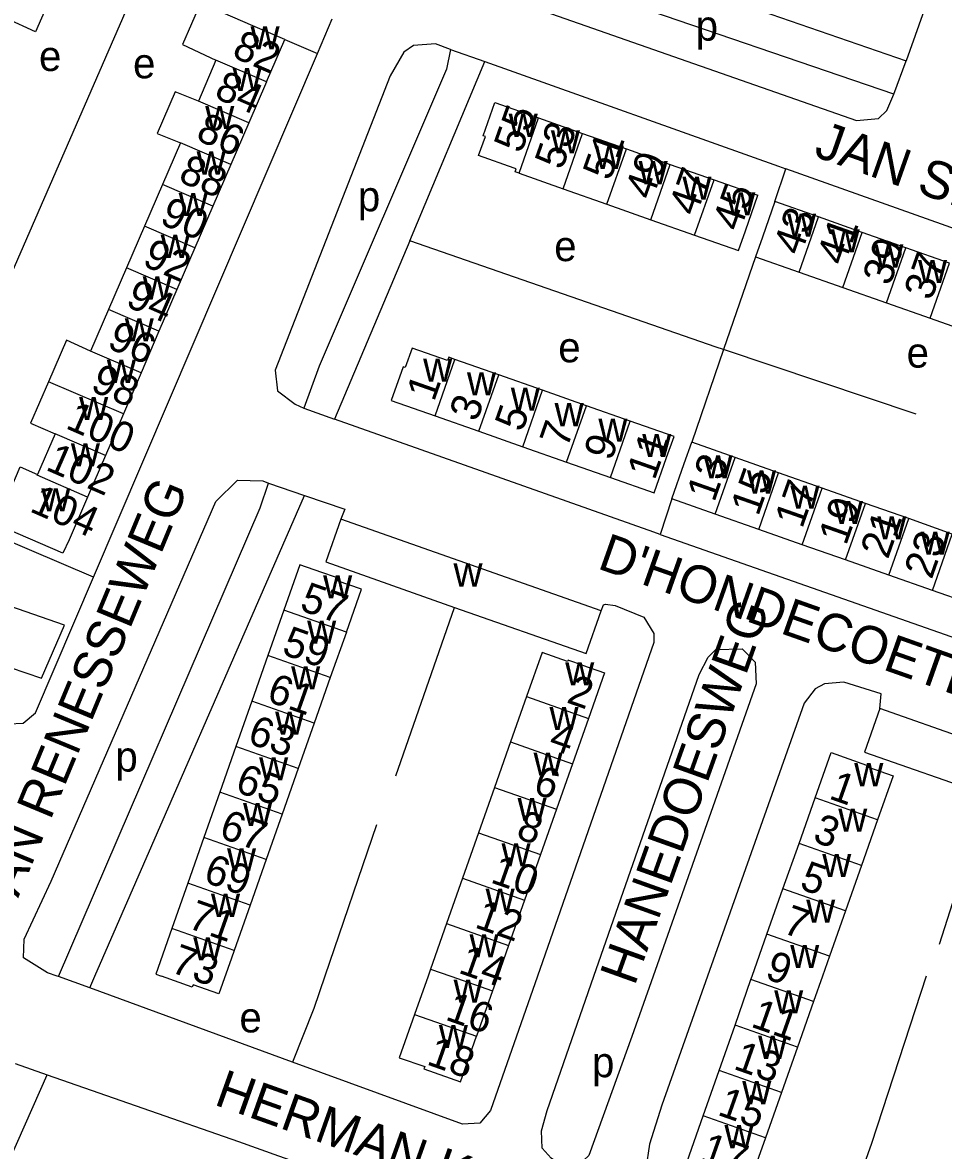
# Model space of a CAD drawing. Extents: x 162804 to 165059, y 381530 to 382901.
# Drawn here: x 163644.1 to 163766.6, y 381726.8 to 381876.8 of the extents above; entities that cross this region are included whole.
import ezdxf

# ---------------------------------------------------------------- set-up
doc = ezdxf.new("R2010")
doc.units = 0
for name, color, linetype in [('BLT_Basislijn', 7, 'Continuous'), ('BLT_Bebouwing', 7, 'Continuous'), ('BLT_Centroide', 7, 'Continuous'), ('BLT_Huisnummer', 7, 'Continuous'), ('BLT_Huisnummer_ tussenligend', 7, 'Continuous'), ('BLT_Onderverdeling_panden', 7, 'Continuous'), ('BLT_Straatnaam', 7, 'Continuous')]:
    doc.layers.add(name, color=color, linetype=linetype)

msp = doc.modelspace()

# ---------------------------------------------------------------- linework, layer by layer
at = {"layer": 'BLT_Basislijn'}
for p, q in [((163629.47, 381813.33), (163659.78, 381882.71)), ((163760.01, 381867.25), (163713.3, 381883.25)), ((163738.48, 381879.67), (163761.67, 381871.69)), ((163683.32, 381872.7), (163685.28, 381877.3)), ((163678.98, 381874.55), (163683.32, 381872.7)), ((163701.04, 381873.2), (163705.58, 381871.61)), ((163653.55, 381803.05), (163683.32, 381872.7)), ((163695.62, 381847.77), (163705.58, 381871.61)), ((163760.01, 381867.25), (163761.67, 381871.69)), ((163744.19, 381852.99), (163745.66, 381857.35)), ((163695.62, 381847.77), (163685.59, 381824.07)), ((163741.61, 381845.66), (163737.37, 381833.31)), ((163737.37, 381833.31), (163733.13, 381820.98)), ((163762.97, 381824.74), (163737.37, 381833.31)), ((163681.54, 381825.53), (163685.59, 381824.07)), ((163676.84, 381815.54), (163681.63, 381813.9)), ((163653.55, 381803.05), (163629.47, 381813.33)), ((163653.73, 381750), (163681.63, 381813.9)), ((163730.48, 381813.47), (163728.92, 381808.74)), ((163693.74, 381776.62), (163701.56, 381799.04)), ((163766.09, 381754.26), (163772.39, 381774.1)), ((163691.19, 381770.14), (163684.3, 381750)), ((163648.87, 381749.95), (163648.71, 381750)), ((163653.04, 381748.44), (163648.87, 381749.95)), ((163653.04, 381748.44), (163653.73, 381750)), ((163680.03, 381738.55), (163653.04, 381748.44)), ((163643.14, 381738.37), (163647.37, 381736.86)), ((163638.42, 381716.6), (163647.37, 381736.86))]:
    msp.add_line(p, q, dxfattribs=at)
for points in [[(163772.36, 381901.83), (163772.22, 381901.46), (163761.67, 381871.69)], [(163713.58, 381878.28), (163755.04, 381863.76), (163757.97, 381864.02), (163759.09, 381865.09), (163760.01, 381867.25)], [(163701.04, 381873.2), (163699.05, 381873.95), (163696.12, 381873.75), (163694.82, 381872.84), (163693.02, 381869.72), (163677.71, 381830.57), (163678.01, 381827.83), (163680.38, 381826.06), (163681.54, 381825.53)], [(163701.04, 381873.2), (163700.49, 381870.58), (163683.54, 381831.12), (163681.54, 381825.53)], [(163705.58, 381871.61), (163744.66, 381857.71), (163745.66, 381857.35)], [(163805.79, 381835.96), (163804.41, 381836.45), (163745.66, 381857.35)], [(163737.37, 381833.31), (163736.36, 381833.65), (163695.62, 381847.77)], [(163605.48, 381823.75), (163598.15, 381806.85), (163597.24, 381803.85), (163596.76, 381800.38), (163598.72, 381798.05), (163642.29, 381783.55), (163644.18, 381783.63), (163645.81, 381785.02), (163653.55, 381803.05)], [(163728.92, 381808.74), (163728.08, 381809.04), (163685.59, 381824.07)], [(163648.71, 381750), (163647.44, 381750.44), (163644.23, 381752.43), (163644.33, 381754.93), (163647.92, 381762.61), (163669.82, 381813.12), (163672.71, 381815.94), (163676.05, 381815.88), (163676.84, 381815.54)], [(163648.87, 381749.95), (163675.72, 381812.25), (163676.84, 381815.54)], [(163681.63, 381813.9), (163686.98, 381812.1), (163686.46, 381810.78)], [(163728.92, 381808.74), (163787.79, 381788.07), (163788.98, 381787.65)], [(163721.08, 381798.59), (163721.37, 381799.36), (163721.66, 381799.46), (163722.93, 381799.3), (163726.76, 381797.74), (163728.1, 381795.55), (163728.06, 381794.38), (163712.6, 381750)], [(163720.12, 381750), (163734.12, 381790.09), (163735.29, 381792.42), (163736.31, 381793.44), (163739.82, 381793.53), (163741.55, 381791.74), (163741.68, 381788.85), (163727.98, 381750)], [(163758.13, 381785.57), (163758.32, 381787.53), (163753.35, 381789.07), (163750.8, 381788.88), (163749.53, 381788.21), (163748.1, 381786.3), (163735.23, 381750)], [(163684.3, 381750), (163682.84, 381745.72), (163680.03, 381738.55)], [(163712.6, 381750), (163706.37, 381732.12), (163704.95, 381730.44), (163702.62, 381730.31), (163680.03, 381738.55)], [(163727.98, 381750), (163725.15, 381741.98), (163719.43, 381726.17), (163718.73, 381725.47), (163717.8, 381725.09), (163715.67, 381724.95), (163714.42, 381725.8), (163713.22, 381727.12), (163713.12, 381729.45), (163713.87, 381732.12), (163720.12, 381750)], [(163735.23, 381750), (163729.15, 381732.86), (163727.51, 381727.67), (163727.02, 381724.4), (163727.01, 381723.23), (163727.33, 381722.52), (163728.51, 381721.39), (163729.94, 381720.75), (163751.94, 381713.38)], [(163764.29, 381750), (163757.03, 381727.74), (163751.94, 381713.38)], [(163647.37, 381736.86), (163672.82, 381728.03), (163678.15, 381726.12), (163737.77, 381705.14), (163743.56, 381703.1), (163751.63, 381700.04), (163751.28, 381698.53)]]:
    msp.add_lwpolyline(points, dxfattribs=at)
at = {"layer": 'BLT_Bebouwing'}
for p, q in [((163676.54, 381868.89), (163678.98, 381874.55)), ((163669.83, 381871.79), (163667.49, 381866.36)), ((163676.54, 381868.89), (163674.2, 381863.47)), ((163712.76, 381864.11), (163718.59, 381862.05)), ((163674.2, 381863.47), (163671.81, 381857.93)), ((163718.59, 381862.05), (163724.43, 381859.99)), ((163665.1, 381860.82), (163662.71, 381855.28)), ((163724.43, 381859.99), (163730.26, 381857.94)), ((163671.81, 381857.93), (163669.42, 381852.38)), ((163710.17, 381856.75), (163716, 381854.69)), ((163730.26, 381857.94), (163736.09, 381855.88)), ((163662.71, 381855.28), (163660.32, 381849.73)), ((163736.09, 381855.88), (163741.92, 381853.83)), ((163716, 381854.69), (163721.83, 381852.64)), ((163669.42, 381852.38), (163667.03, 381846.84)), ((163721.83, 381852.64), (163727.67, 381850.58)), ((163750, 381850.95), (163744.19, 381852.99)), ((163727.67, 381850.58), (163733.5, 381848.53)), ((163755.8, 381848.9), (163750, 381850.95)), ((163660.32, 381849.73), (163657.93, 381844.18)), ((163761.61, 381846.85), (163755.8, 381848.9)), ((163667.03, 381846.84), (163664.64, 381841.29)), ((163767.41, 381844.81), (163761.61, 381846.85)), ((163741.61, 381845.66), (163747.41, 381843.61)), ((163657.93, 381844.18), (163655.54, 381838.64)), ((163747.41, 381843.61), (163753.22, 381841.57)), ((163664.64, 381841.29), (163662.25, 381835.75)), ((163753.22, 381841.57), (163759.02, 381839.52)), ((163655.54, 381838.64), (163653.15, 381833.1)), ((163759.02, 381839.52), (163764.83, 381837.47)), ((163764.83, 381837.47), (163770.63, 381835.43)), ((163662.25, 381835.75), (163659.86, 381830.2)), ((163707.46, 381829.95), (163701.63, 381832)), ((163659.86, 381830.2), (163657.51, 381824.75)), ((163713.29, 381827.9), (163707.46, 381829.95)), ((163719.11, 381825.85), (163713.29, 381827.9)), ((163724.94, 381823.8), (163719.11, 381825.85)), ((163657.51, 381824.75), (163655.13, 381819.23)), ((163698.99, 381824.49), (163704.82, 381822.45)), ((163648.42, 381822.12), (163646.09, 381816.71)), ((163704.82, 381822.45), (163710.65, 381820.4)), ((163738.9, 381818.95), (163733.13, 381820.98)), ((163655.13, 381819.23), (163652.76, 381813.71)), ((163710.65, 381820.4), (163716.47, 381818.35)), ((163716.47, 381818.35), (163722.3, 381816.3)), ((163744.68, 381816.92), (163738.9, 381818.95)), ((163722.3, 381816.3), (163728.13, 381814.25)), ((163750.46, 381814.89), (163744.68, 381816.92)), ((163756.23, 381812.86), (163750.46, 381814.89)), ((163736.26, 381811.43), (163730.48, 381813.47)), ((163762.01, 381810.83), (163756.23, 381812.86)), ((163686.46, 381810.78), (163684.45, 381805.07)), ((163721.08, 381798.59), (163686.46, 381810.78)), ((163742.04, 381809.4), (163736.26, 381811.43)), ((163767.78, 381808.79), (163762.01, 381810.83)), ((163747.81, 381807.37), (163742.04, 381809.4)), ((163753.59, 381805.34), (163747.81, 381807.37)), ((163684.45, 381805.07), (163701.56, 381799.04)), ((163759.36, 381803.31), (163753.59, 381805.34)), ((163765.14, 381801.28), (163759.36, 381803.31)), ((163770.92, 381799.24), (163765.14, 381801.28)), ((163678.87, 381798.67), (163676.74, 381792.62)), ((163701.56, 381799.04), (163719.07, 381792.88)), ((163719.07, 381792.88), (163721.08, 381798.59)), ((163687.18, 381795.75), (163685.04, 381789.7)), ((163676.74, 381792.62), (163674.61, 381786.57)), ((163685.04, 381789.7), (163682.91, 381783.65)), ((163674.61, 381786.57), (163672.48, 381780.52)), ((163711.14, 381787.18), (163709.01, 381781.14)), ((163792.74, 381773.48), (163758.13, 381785.57)), ((163682.91, 381783.65), (163680.78, 381777.6)), ((163719.38, 381784.28), (163717.26, 381778.24)), ((163672.48, 381780.52), (163670.35, 381774.47)), ((163709.01, 381781.14), (163706.89, 381775.1)), ((163680.78, 381777.6), (163678.65, 381771.55)), ((163717.26, 381778.24), (163715.13, 381772.2)), ((163670.35, 381774.47), (163668.22, 381768.42)), ((163706.89, 381775.1), (163704.76, 381769.06)), ((163747.4, 381767.66), (163749.53, 381773.7)), ((163678.65, 381771.55), (163676.52, 381765.49)), ((163715.13, 381772.2), (163713, 381766.16)), ((163757.83, 381770.78), (163755.7, 381764.73)), ((163668.22, 381768.42), (163666.09, 381762.37)), ((163704.76, 381769.06), (163702.63, 381763.02)), ((163745.26, 381761.62), (163747.4, 381767.66)), ((163676.52, 381765.49), (163674.39, 381759.45)), ((163713, 381766.16), (163710.88, 381760.12)), ((163755.7, 381764.73), (163753.57, 381758.69)), ((163666.09, 381762.37), (163663.96, 381756.32)), ((163702.63, 381763.02), (163700.5, 381756.98)), ((163743.13, 381755.58), (163745.26, 381761.62)), ((163674.39, 381759.45), (163672.26, 381753.4)), ((163710.88, 381760.12), (163708.75, 381754.08)), ((163753.57, 381758.69), (163751.44, 381752.65)), ((163700.5, 381756.98), (163698.38, 381750.95)), ((163741.17, 381750), (163743.13, 381755.58)), ((163708.75, 381754.08), (163707.31, 381750)), ((163751.44, 381752.65), (163750.5, 381750)), ((163698.38, 381750.95), (163698.04, 381750)), ((163698.04, 381750), (163696.25, 381744.91)), ((163707.31, 381750), (163706.62, 381748.04)), ((163738.88, 381743.49), (163741, 381749.54)), ((163741, 381749.54), (163741.17, 381750)), ((163750.5, 381750), (163749.31, 381746.61)), ((163706.62, 381748.04), (163704.5, 381742)), ((163749.31, 381746.61), (163747.18, 381740.57)), ((163736.75, 381737.45), (163738.88, 381743.49)), ((163747.18, 381740.57), (163745.05, 381734.53)), ((163734.63, 381731.41), (163736.75, 381737.45)), ((163745.05, 381734.53), (163742.92, 381728.49))]:
    msp.add_line(p, q, dxfattribs=at)
for points in [[(163644.36, 381882.87), (163648.21, 381881.06), (163645.82, 381875.56), (163641.95, 381877.35)], [(163667.77, 381879.36), (163665.39, 381873.89), (163669.83, 381871.79)], [(163678.98, 381874.55), (163674.74, 381876.38), (163667.77, 381879.36)], [(163667.49, 381866.36), (163664.39, 381867.58), (163662.02, 381862.06), (163665.1, 381860.82)], [(163710.17, 381856.75), (163709.62, 381856.94), (163709.76, 381857.35), (163709.49, 381857.44), (163704.77, 381859.1), (163705.67, 381861.65), (163705.37, 381861.75), (163706.93, 381866.16), (163712.76, 381864.11)], [(163733.5, 381848.53), (163739.33, 381846.47), (163740.26, 381849.12), (163741.92, 381853.83)], [(163744.19, 381852.99), (163742.53, 381848.28), (163741.61, 381845.66)], [(163653.15, 381833.1), (163649.93, 381834.56), (163647.55, 381829.04)], [(163701.63, 381832), (163700.8, 381832.29), (163700.64, 381831.86), (163695.92, 381833.52), (163695, 381830.91), (163694.73, 381831.01), (163693.16, 381826.55), (163698.99, 381824.49)], [(163647.55, 381829.04), (163645.18, 381823.53), (163648.42, 381822.12)], [(163728.13, 381814.25), (163729.78, 381818.95), (163730.77, 381821.75), (163724.94, 381823.8)], [(163730.48, 381813.47), (163732.13, 381818.15), (163733.13, 381820.98)], [(163652.76, 381813.71), (163650.3, 381808.02), (163649.45, 381806.26), (163640.52, 381810.11), (163643.79, 381817.7), (163646.09, 381816.71)], [(163683.92, 381803.68), (163681, 381804.71), (163678.87, 381798.67)], [(163687.18, 381795.75), (163689.18, 381801.44), (163685.96, 381802.57), (163686.08, 381802.92), (163685.72, 381803.05), (163683.92, 381803.68)], [(163635.09, 381790.93), (163641.64, 381788.69), (163642.45, 381791.06), (163646.63, 381789.62), (163649.68, 381796.66), (163638.29, 381800.6)], [(163718.57, 381791.35), (163716.79, 381791.97), (163716.67, 381792.02), (163716.61, 381791.85), (163713.21, 381793.04), (163711.14, 381787.18)], [(163718.57, 381791.35), (163721.51, 381790.31), (163719.38, 381784.28)], [(163758.13, 381785.57), (163756.11, 381779.79), (163772.39, 381774.1)], [(163749.53, 381773.7), (163751.66, 381779.74), (163756.37, 381778.07), (163756.57, 381778), (163756.52, 381777.85), (163759.9, 381776.64), (163757.83, 381770.78)], [(163663.96, 381756.32), (163661.82, 381750.27), (163662.59, 381750)], [(163672.26, 381753.4), (163671.91, 381752.41), (163670.21, 381747.65)], [(163670.21, 381747.65), (163666.79, 381748.85), (163666.68, 381748.53), (163662.59, 381750)], [(163696.25, 381744.91), (163694.22, 381739.16), (163697.61, 381737.97), (163697.5, 381737.67), (163702.37, 381735.96), (163704.5, 381742)], [(163742.92, 381728.49), (163740.87, 381722.67), (163737.41, 381723.9), (163737.32, 381723.66), (163732.5, 381725.36), (163734.63, 381731.41)]]:
    msp.add_lwpolyline(points, dxfattribs=at)
at = {"layer": 'BLT_Onderverdeling_panden'}
for p, q in [((163676.54, 381868.89), (163669.83, 381871.79)), ((163674.2, 381863.47), (163667.49, 381866.36)), ((163710.17, 381856.75), (163712.76, 381864.11)), ((163716, 381854.69), (163718.59, 381862.05)), ((163671.81, 381857.93), (163665.1, 381860.82)), ((163721.83, 381852.64), (163724.43, 381859.99)), ((163727.67, 381850.58), (163730.26, 381857.94)), ((163669.42, 381852.38), (163662.71, 381855.28)), ((163733.5, 381848.53), (163736.09, 381855.88)), ((163747.41, 381843.61), (163750, 381850.95)), ((163667.03, 381846.84), (163660.32, 381849.73)), ((163753.22, 381841.57), (163755.8, 381848.9)), ((163759.02, 381839.52), (163761.61, 381846.85)), ((163764.83, 381837.47), (163767.41, 381844.81)), ((163664.64, 381841.29), (163657.93, 381844.18)), ((163662.25, 381835.75), (163655.54, 381838.64)), ((163659.86, 381830.2), (163653.15, 381833.1)), ((163698.99, 381824.49), (163701.63, 381832)), ((163704.82, 381822.45), (163707.46, 381829.95)), ((163657.51, 381824.75), (163647.55, 381829.04)), ((163710.65, 381820.4), (163713.29, 381827.9)), ((163716.47, 381818.35), (163719.11, 381825.85)), ((163722.3, 381816.3), (163724.94, 381823.8)), ((163655.13, 381819.23), (163648.42, 381822.12)), ((163736.26, 381811.43), (163738.9, 381818.95)), ((163742.04, 381809.4), (163744.68, 381816.92)), ((163747.81, 381807.37), (163750.46, 381814.89)), ((163753.59, 381805.34), (163756.23, 381812.86)), ((163759.36, 381803.31), (163762.01, 381810.83)), ((163765.14, 381801.28), (163767.78, 381808.79)), ((163687.18, 381795.75), (163678.87, 381798.67)), ((163685.04, 381789.7), (163676.74, 381792.62)), ((163682.91, 381783.65), (163674.61, 381786.57)), ((163711.14, 381787.18), (163719.38, 381784.28)), ((163680.78, 381777.6), (163672.48, 381780.52)), ((163709.01, 381781.14), (163717.26, 381778.24)), ((163678.65, 381771.55), (163670.35, 381774.47)), ((163706.89, 381775.1), (163715.13, 381772.2)), ((163757.83, 381770.78), (163749.53, 381773.7)), ((163676.52, 381765.49), (163668.22, 381768.42)), ((163704.76, 381769.06), (163713, 381766.16)), ((163755.7, 381764.73), (163747.4, 381767.66)), ((163674.39, 381759.45), (163666.09, 381762.37)), ((163702.63, 381763.02), (163710.88, 381760.12)), ((163753.57, 381758.69), (163745.26, 381761.62)), ((163672.26, 381753.4), (163663.96, 381756.32)), ((163700.5, 381756.98), (163708.75, 381754.08)), ((163751.44, 381752.65), (163743.13, 381755.58)), ((163698.38, 381750.95), (163701.06, 381750)), ((163701.06, 381750), (163706.62, 381748.04)), ((163749.31, 381746.61), (163741, 381749.54)), ((163696.25, 381744.91), (163704.5, 381742)), ((163747.18, 381740.57), (163738.88, 381743.49)), ((163745.05, 381734.53), (163736.75, 381737.45)), ((163742.92, 381728.49), (163734.63, 381731.41))]:
    msp.add_line(p, q, dxfattribs=at)
msp.add_lwpolyline([(163652.76, 381813.71), (163646.04, 381816.6), (163646.09, 381816.71)], dxfattribs=at)

# ---------------------------------------------------------------- texts
at = {"layer": 'BLT_Centroide'}
for s, p in [('w', (163674.43, 381873.22)), ('p', (163733.64, 381874.39)), ('e', (163646.29, 381870.35)), ('e', (163658.8, 381869.38)), ('w', (163672.04, 381867.69)), ('w', (163668.4, 381862.62)), ('w', (163708.77, 381861.59)), ('w', (163714.38, 381859.39)), ('w', (163667.26, 381856.59)), ('w', (163720.22, 381857.34)), ('w', (163726.05, 381855.3)), ('w', (163731.88, 381853.23)), ('w', (163664.87, 381851.06)), ('p', (163688.71, 381851.7)), ('w', (163737.72, 381851.17)), ('w', (163745.8, 381848.31)), ('w', (163751.61, 381846.25)), ('w', (163662.48, 381845.5)), ('e', (163714.83, 381845.07)), ('w', (163757.41, 381844.22)), ('w', (163763.22, 381842.16)), ('w', (163660.09, 381839.97)), ('w', (163657.7, 381834.41)), ('e', (163715.37, 381831.62)), ('e', (163761.71, 381830.91)), ('w', (163655.31, 381828.88)), ('w', (163697.39, 381829.03)), ('w', (163703.22, 381827.22)), ('w', (163709.05, 381825.17)), ('w', (163651.63, 381823.94)), ('w', (163714.88, 381823.12)), ('w', (163720.7, 381821.06)), ('w', (163726.53, 381819.03)), ('w', (163650.53, 381817.78)), ('w', (163734.69, 381816.2)), ('w', (163740.47, 381814.17)), ('w', (163646.59, 381811.81)), ('w', (163746.25, 381812.14)), ('w', (163752.02, 381810.11)), ('w', (163757.8, 381808.08)), ('w', (163763.58, 381806.05)), ('w', (163701.43, 381801.81)), ('w', (163684.09, 381800.22)), ('w', (163681.96, 381794.19)), ('w', (163679.83, 381788.12)), ('w', (163716.29, 381788.66)), ('w', (163677.7, 381782.09)), ('w', (163714.2, 381782.72)), ('p', (163656.45, 381777.2)), ('w', (163675.57, 381776.03)), ('w', (163712.07, 381776.66)), ('w', (163754.74, 381775.25)), ('w', (163673.43, 381769.97)), ('w', (163709.95, 381770.62)), ('w', (163752.61, 381769.22)), ('w', (163671.3, 381763.94)), ('w', (163707.82, 381764.59)), ('w', (163750.48, 381763.19)), ('w', (163669.17, 381757.88)), ('w', (163705.7, 381758.56)), ('w', (163748.35, 381757.12)), ('w', (163666.81, 381752.09)), ('w', (163703.56, 381752.5)), ('w', (163746.22, 381751.09)), ('w', (163701.44, 381746.47)), ('w', (163744.09, 381745.06)), ('e', (163672.95, 381742.52)), ('w', (163699.48, 381740.44)), ('w', (163741.96, 381739)), ('p', (163719.85, 381736.56)), ('w', (163739.84, 381732.97)), ('w', (163737.48, 381727.12))]:
    msp.add_text(s, height=4, dxfattribs=at).set_placement(p)
at = {"layer": 'BLT_Huisnummer'}
for s, rotation, p in [('82', 336.4706, (163671.8, 381872.29)), ('55', 70.5803, (163710.45, 381859.28)), ('86', 336.4706, (163666.99, 381861.28)), ('51', 70.5803, (163722.28, 381855.65)), ('47', 70.5829, (163733.71, 381850.93)), ('90', 336.4706, (163662.19, 381850.1)), ('43', 70.5771, (163747.62, 381845.68)), ('39', 70.5841, (163759.49, 381841.66)), ('94', 336.4706, (163657.65, 381839.15)), ('98', 336.4706, (163652.98, 381827.91)), ('1', 70.6195, (163698.84, 381826.28)), ('5', 70.6171, (163710.58, 381822.23)), ('9', 70.6237, (163722.43, 381818.38)), ('13', 70.6238, (163736.12, 381812.91)), ('104', 336.4706, (163644.9, 381811.85)), ('17', 70.6214, (163747.81, 381809.4)), ('21', 70.621, (163759.21, 381805.33)), ('57', 340.5975, (163680.81, 381798.72)), ('61', 340.5935, (163676.41, 381786.61)), ('2', 340.6047, (163716.33, 381786.43)), ('65', 340.5935, (163672.22, 381774.59)), ('6', 340.6029, (163711.85, 381774.38)), ('1', 340.5957, (163751.23, 381773.65)), ('69', 340.5997, (163667.99, 381762.6)), ('10', 340.6032, (163706.21, 381762.5)), ('5', 340.5939, (163747.32, 381761.65)), ('73', 340.2513, (163663.63, 381750.61)), ('14', 340.6014, (163701.93, 381750.49)), ('9', 340.5932, (163742.72, 381749.73)), ('18', 340.613, (163697.71, 381738.31)), ('13', 340.5925, (163738.53, 381737.71)), ('17', 340.5625, (163734.08, 381725.53))]:
    msp.add_text(s, height=4, rotation=rotation, dxfattribs=at).set_placement(p)
at = {"layer": 'BLT_Huisnummer_ tussenligend'}
for s, rotation, p in [('84', 336.4706, (163669.44, 381866.87)), ('53', 70.5803, (163715.89, 381857.08)), ('88', 336.4706, (163664.66, 381855.75)), ('49', 70.5829, (163727.87, 381853.07)), ('45', 70.5771, (163739.52, 381848.87)), ('41', 70.5841, (163753.4, 381844.34)), ('92', 336.4706, (163659.88, 381844.56)), ('37', 70.5841, (163765, 381839.7)), ('96', 336.4706, (163655.19, 381833.61)), ('3', 70.6195, (163704.54, 381823.59)), ('100', 336.4706, (163649.68, 381822.91)), ('7', 70.6171, (163716.55, 381820.09)), ('11', 70.6237, (163728.18, 381815.83)), ('102', 336.4706, (163647.03, 381817.37)), ('15', 70.6238, (163741.96, 381811.05)), ('19', 70.6214, (163753.65, 381807.15)), ('23', 70.621, (163765.04, 381802.65)), ('59', 340.5975, (163678.43, 381792.87)), ('63', 340.5935, (163673.86, 381781.04)), ('4', 340.6047, (163713.92, 381780.33)), ('67', 340.5935, (163670.08, 381768.49)), ('8', 340.6029, (163709.6, 381768.4)), ('3', 340.5957, (163749.07, 381767.95)), ('71', 340.5997, (163665.9, 381756.47)), ('12', 340.6032, (163704.11, 381756.52)), ('7', 340.5939, (163745.05, 381755.81)), ('16', 340.6014, (163700.2, 381744.25)), ('11', 340.5932, (163740.84, 381743.32)), ('15', 340.5925, (163736.41, 381731.6))]:
    msp.add_text(s, height=4, rotation=rotation, dxfattribs=at).set_placement(p)
at = {"layer": 'BLT_Straatnaam'}
for s, rotation, p in [('JAN SLUYTERSWEG', 340.564, (163749.21, 381859.07)), ('VAN RENESSEWEG', 67.4162, (163641.8, 381756.22)), ("D'HONDECOETERSTRAAT", 340.5203, (163720.42, 381804.26)), ('HANEDOESWEG', 70.2943, (163725.52, 381748.59)), ('HERMAN KRUIJDERSTRAAT', 340.4021, (163669.43, 381732.96))]:
    msp.add_text(s, height=5, rotation=rotation, dxfattribs=at).set_placement(p)

doc.saveas('drawing.dxf')
